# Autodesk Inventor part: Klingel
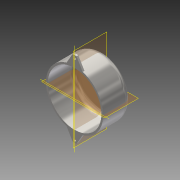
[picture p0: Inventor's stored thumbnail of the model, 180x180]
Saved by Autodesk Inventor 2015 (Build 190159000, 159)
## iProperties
Created: 2015-03
Part Number: Klingel
Material: Titan
Document SubType Name: Modeling
Designer: Manuel
Density: 4.51 g/cm^3
Appearance: Titan
Author: Manuel
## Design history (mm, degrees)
sketch "Skizze1"
  geometry: L1 (8.78, -30.252)-(0, -45.777); L2 (0, -45.777)-(-8.78, -30.252); L3 (0, -64.087)-(0, 64.087) reference; L4 (44.1, 0)-(-44.1, 0) reference; L5 (0, 45.777)-(-8.78, 30.252); L6 (8.78, 30.252)-(0, 45.777); A1 r 31.5 centre (0, 0) between (8.78, -30.252) and (-8.78, -30.252); 1 further point
  constraints: 8 end point, 3 symmetric about line, 2 point on circle, 1 centre point, 1 coincident
  dimensions: "d0" = 63 diameter of A1
extrude "Extrusion1" new body sketch "Skizze1" distance "d1" = 32; taper "d2" = 0 deg
sketch "Skizze2"
  geometry: L1 (-8.874, -30.224)-(0, -45.4); L2 (0, -45.4)-(8.874, -30.224); L3 (-44.1, 0)-(44.1, 0) reference; L4 (-8.874, 30.224)-(0, 45.4); L5 (0, 45.4)-(8.874, 30.224); A1 r 31.5 centre (0, 0) between (-8.874, -30.224) and (8.874, -30.224) reference; 1 further point
  constraints: 8 end point, 3 symmetric about line, 2 point on circle
extrude "Extrusion2" join sketch "Skizze2" distance "d3" = 2; taper "d4" = 0 deg
fillet "Rundung1" dims "d5" = 8
sketch "Skizze3"
  geometry: L1 (5.159, 37.602)-(5.159, 51.031); L2 (5.159, 51.031)-(-5.047, 51.031); L3 (-5.047, 51.031)-(-5.047, 38.13); A1 r 5.225 centre (0, 36.778) between (5.159, 37.602) and (-5.047, 38.13); 1 further point
  constraints: 6 end point, 3 point on circle, 2 perpendicular, 1 centre point, 1 vertical
extrude "Extrusion3" cut sketch "Skizze3" distance "d6" = 2; taper "d7" = 0 deg
fillet "Rundung2" dims "d8" = 1
fillet "Rundung3" dims "d9" = 1
hole "Bohrung1" diameter "d12" = 3; stored, may be unused: countersink angle "d16" = 90 deg, drill point angle "d18" = 118 deg; dims "d10" = 10, "d11" = 10, "d13" = 6, "d14" = 4, "d15" = 2, "d17" = 8
mirror "Spiegeln1"
feature "Wandung1" dims "d19" = 2
sketch "Skizze5"
  geometry: L1 (0, 58.804)-(0, -58.804) reference; C1 r 3 at (0, 0); 1 further point
  constraints: 1 centre point, 1 coincident
  dimensions: "d20" = 6 diameter of C1
extrude "Extrusion4" join sketch "Skizze5" distance "d21" = 2; taper "d22" = 0 deg
sketch "Skizze7"
  geometry: L1 (0.966, 3.654)-(-1.027, 3.654); L2 (-1.027, 3.654)-(-1.027, -3.694); L3 (-1.027, -3.694)-(0.966, -3.694); L4 (0.966, -3.694)-(0.966, 3.654); C1 r 3 at (0, 0) reference; 1 further point
  constraints: 8 end point, 2 parallel, 1 horizontal, 1 perpendicular
extrude "Extrusion5" cut sketch "Skizze7" distance "d23" = 1; taper "d24" = 0 deg
node "Volumenkörper1"
